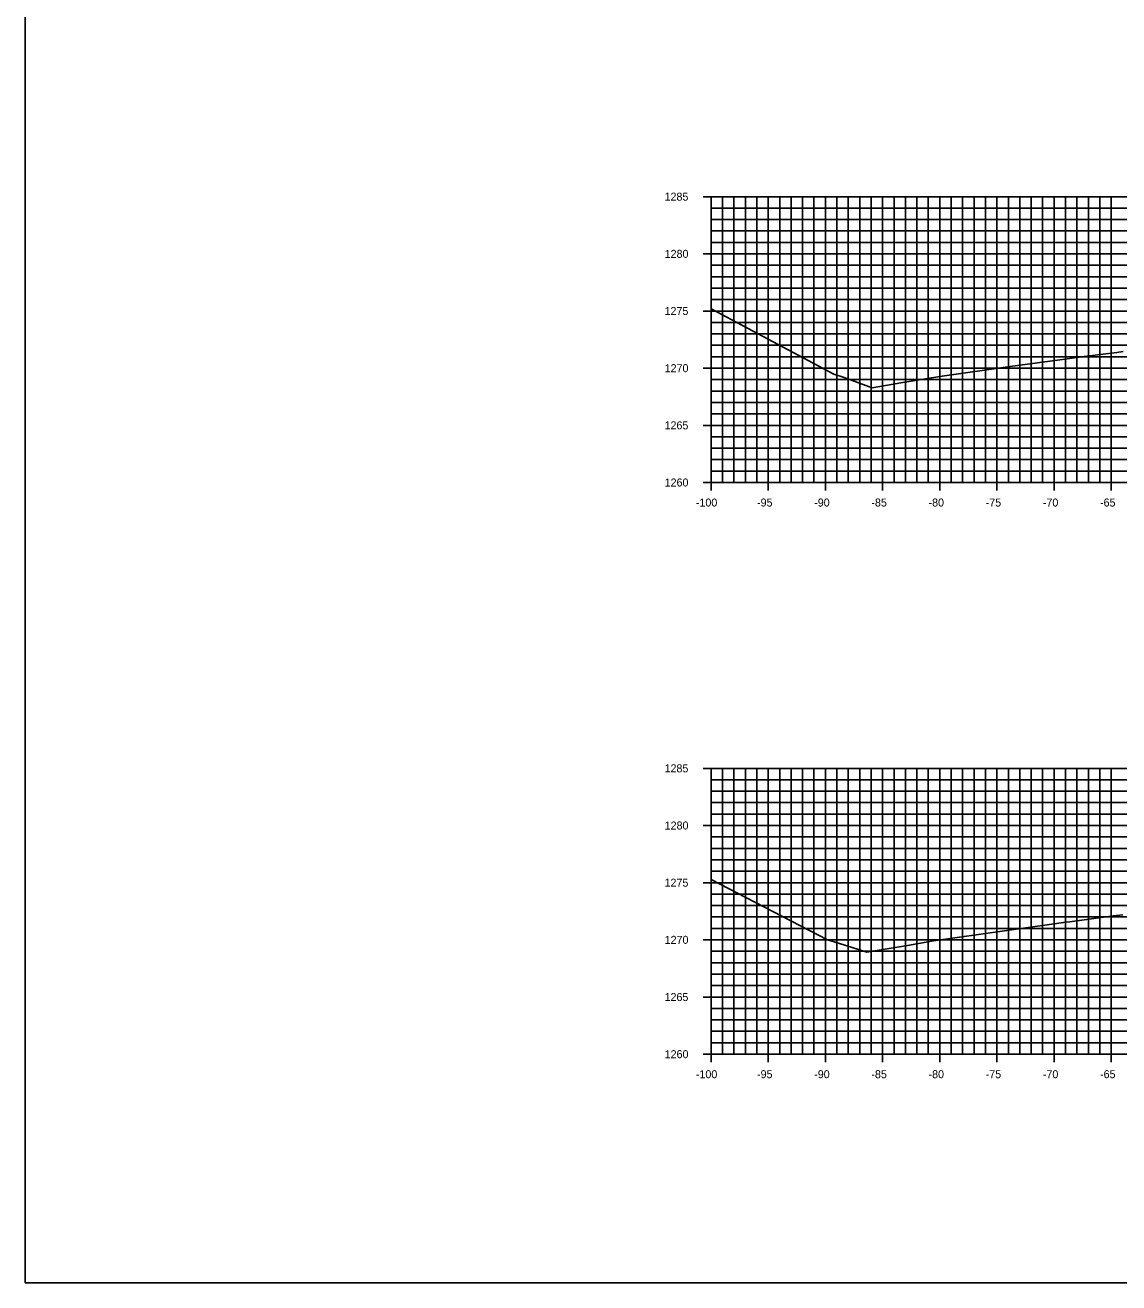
# Model space of a CAD drawing. Extents: x 674939 to 678919, y 750652 to 765176.
# Drawn here: x 678578.5 to 678674.2, y 756672.6 to 756782.6 of the extents above; entities that cross this region are included whole.
import ezdxf

# ---------------------------------------------------------------- set-up
doc = ezdxf.new("R2010")
doc.units = 0
for name, color, linetype in [('R_Axis', 7, 'Continuous'), ('R_Axis Annot', 7, 'Continuous'), ('R_Exist Surface', 7, 'Continuous'), ('R_Grid', 7, 'Continuous'), ('R_No Plot', 7, 'Continuous')]:
    doc.layers.add(name, color=color, linetype=linetype)

msp = doc.modelspace()

# ---------------------------------------------------------------- linework, layer by layer
at = {"layer": 'R_Axis'}
for p, q in [((678637.83, 756767.55), (678639.23, 756767.55)), ((678638.53, 756742.55), (678638.53, 756767.55)), ((678638.53, 756766.55), (678638.88, 756766.55)), ((678638.53, 756765.55), (678638.88, 756765.55)), ((678638.53, 756764.55), (678638.88, 756764.55)), ((678638.53, 756763.55), (678638.88, 756763.55)), ((678637.83, 756762.55), (678639.23, 756762.55)), ((678638.53, 756761.55), (678638.88, 756761.55)), ((678638.53, 756760.55), (678638.88, 756760.55)), ((678638.53, 756759.55), (678638.88, 756759.55)), ((678638.53, 756758.55), (678638.88, 756758.55)), ((678637.83, 756757.55), (678639.23, 756757.55)), ((678638.53, 756756.55), (678638.88, 756756.55)), ((678638.53, 756755.55), (678638.88, 756755.55)), ((678638.53, 756754.55), (678638.88, 756754.55)), ((678638.53, 756753.55), (678638.88, 756753.55)), ((678637.83, 756752.55), (678639.23, 756752.55)), ((678638.53, 756751.55), (678638.88, 756751.55)), ((678638.53, 756750.55), (678638.88, 756750.55)), ((678638.53, 756749.55), (678638.88, 756749.55)), ((678638.53, 756748.55), (678638.88, 756748.55)), ((678637.83, 756747.55), (678639.23, 756747.55)), ((678638.53, 756746.55), (678638.88, 756746.55)), ((678638.53, 756745.55), (678638.88, 756745.55)), ((678638.53, 756744.55), (678638.88, 756744.55)), ((678638.53, 756743.55), (678638.88, 756743.55)), ((678638.53, 756741.85), (678638.53, 756743.25)), ((678643.53, 756741.85), (678643.53, 756743.25)), ((678648.53, 756741.85), (678648.53, 756743.25)), ((678653.53, 756741.85), (678653.53, 756743.25)), ((678658.53, 756741.85), (678658.53, 756743.25)), ((678663.53, 756741.85), (678663.53, 756743.25)), ((678668.53, 756741.85), (678668.53, 756743.25)), ((678673.53, 756741.85), (678673.53, 756743.25)), ((678637.83, 756742.55), (678639.23, 756742.55)), ((678638.53, 756742.55), (678838.53, 756742.55)), ((678637.83, 756717.55), (678639.23, 756717.55)), ((678638.53, 756692.55), (678638.53, 756717.55)), ((678638.53, 756716.55), (678638.88, 756716.55)), ((678638.53, 756715.55), (678638.88, 756715.55)), ((678638.53, 756714.55), (678638.88, 756714.55)), ((678638.53, 756713.55), (678638.88, 756713.55)), ((678637.83, 756712.55), (678639.23, 756712.55)), ((678638.53, 756711.55), (678638.88, 756711.55)), ((678638.53, 756710.55), (678638.88, 756710.55)), ((678638.53, 756709.55), (678638.88, 756709.55)), ((678638.53, 756708.55), (678638.88, 756708.55)), ((678637.83, 756707.55), (678639.23, 756707.55)), ((678638.53, 756706.55), (678638.88, 756706.55)), ((678638.53, 756705.55), (678638.88, 756705.55)), ((678638.53, 756704.55), (678638.88, 756704.55)), ((678638.53, 756703.55), (678638.88, 756703.55)), ((678637.83, 756702.55), (678639.23, 756702.55)), ((678638.53, 756701.55), (678638.88, 756701.55)), ((678638.53, 756700.55), (678638.88, 756700.55)), ((678638.53, 756699.55), (678638.88, 756699.55)), ((678638.53, 756698.55), (678638.88, 756698.55)), ((678637.83, 756697.55), (678639.23, 756697.55)), ((678638.53, 756696.55), (678638.88, 756696.55)), ((678638.53, 756695.55), (678638.88, 756695.55)), ((678638.53, 756694.55), (678638.88, 756694.55)), ((678638.53, 756693.55), (678638.88, 756693.55)), ((678637.83, 756692.55), (678639.23, 756692.55)), ((678638.53, 756691.85), (678638.53, 756693.25)), ((678638.53, 756692.55), (678838.53, 756692.55)), ((678643.53, 756691.85), (678643.53, 756693.25)), ((678648.53, 756691.85), (678648.53, 756693.25)), ((678653.53, 756691.85), (678653.53, 756693.25)), ((678658.53, 756691.85), (678658.53, 756693.25)), ((678663.53, 756691.85), (678663.53, 756693.25)), ((678668.53, 756691.85), (678668.53, 756693.25)), ((678673.53, 756691.85), (678673.53, 756693.25))]:
    msp.add_line(p, q, dxfattribs=at)
at = {"layer": 'R_Exist Surface'}
for points in [[(678638.53, 756757.73), (678641.72, 756756.04), (678649.26, 756752.04), (678650.17, 756751.74), (678652.61, 756750.82), (678655.13, 756751.26), (678658.54, 756751.82), (678664.68, 756752.69), (678669.48, 756753.33), (678671.17, 756753.56), (678674.02, 756753.93), (678674.57, 756754.01)], [(678638.53, 756707.83), (678641.56, 756706.26), (678648.72, 756702.56), (678649.68, 756702.25), (678652.14, 756701.46), (678655.72, 756702.06), (678657.98, 756702.45), (678668.32, 756703.91), (678669.56, 756704.09), (678669.92, 756704.14), (678673.69, 756704.65), (678673.72, 756704.65), (678674.53, 756704.75)]]:
    msp.add_lwpolyline(points, dxfattribs=at)
at = {"layer": 'R_Grid'}
for p, q in [((678638.53, 756767.55), (678838.53, 756767.55)), ((678638.53, 756742.55), (678638.53, 756767.55)), ((678639.53, 756742.55), (678639.53, 756767.55)), ((678640.53, 756742.55), (678640.53, 756767.55)), ((678641.53, 756742.55), (678641.53, 756767.55)), ((678642.53, 756742.55), (678642.53, 756767.55)), ((678643.53, 756742.55), (678643.53, 756767.55)), ((678644.53, 756742.55), (678644.53, 756767.55)), ((678645.53, 756742.55), (678645.53, 756767.55)), ((678646.53, 756742.55), (678646.53, 756767.55)), ((678647.53, 756742.55), (678647.53, 756767.55)), ((678648.53, 756742.55), (678648.53, 756767.55)), ((678649.53, 756742.55), (678649.53, 756767.55)), ((678650.53, 756742.55), (678650.53, 756767.55)), ((678651.53, 756742.55), (678651.53, 756767.55)), ((678652.53, 756742.55), (678652.53, 756767.55)), ((678653.53, 756742.55), (678653.53, 756767.55)), ((678654.53, 756742.55), (678654.53, 756767.55)), ((678655.53, 756742.55), (678655.53, 756767.55)), ((678656.53, 756742.55), (678656.53, 756767.55)), ((678657.53, 756742.55), (678657.53, 756767.55)), ((678658.53, 756742.55), (678658.53, 756767.55)), ((678659.53, 756742.55), (678659.53, 756767.55)), ((678660.53, 756742.55), (678660.53, 756767.55)), ((678661.53, 756742.55), (678661.53, 756767.55)), ((678662.53, 756742.55), (678662.53, 756767.55)), ((678663.53, 756742.55), (678663.53, 756767.55)), ((678664.53, 756742.55), (678664.53, 756767.55)), ((678665.53, 756742.55), (678665.53, 756767.55)), ((678666.53, 756742.55), (678666.53, 756767.55)), ((678667.53, 756742.55), (678667.53, 756767.55)), ((678668.53, 756742.55), (678668.53, 756767.55)), ((678669.53, 756742.55), (678669.53, 756767.55)), ((678670.53, 756742.55), (678670.53, 756767.55)), ((678671.53, 756742.55), (678671.53, 756767.55)), ((678672.53, 756742.55), (678672.53, 756767.55)), ((678673.53, 756742.55), (678673.53, 756767.55)), ((678638.53, 756766.55), (678838.53, 756766.55)), ((678638.53, 756765.55), (678838.53, 756765.55)), ((678638.53, 756764.55), (678838.53, 756764.55)), ((678638.53, 756763.55), (678838.53, 756763.55)), ((678638.53, 756762.55), (678838.53, 756762.55)), ((678638.53, 756761.55), (678838.53, 756761.55)), ((678638.53, 756760.55), (678838.53, 756760.55)), ((678638.53, 756759.55), (678838.53, 756759.55)), ((678638.53, 756758.55), (678838.53, 756758.55)), ((678638.53, 756757.55), (678838.53, 756757.55)), ((678638.53, 756756.55), (678838.53, 756756.55)), ((678638.53, 756755.55), (678838.53, 756755.55)), ((678638.53, 756754.55), (678838.53, 756754.55)), ((678638.53, 756753.55), (678838.53, 756753.55)), ((678638.53, 756752.55), (678838.53, 756752.55)), ((678638.53, 756751.55), (678838.53, 756751.55)), ((678638.53, 756750.55), (678838.53, 756750.55)), ((678638.53, 756749.55), (678838.53, 756749.55)), ((678638.53, 756748.55), (678838.53, 756748.55)), ((678638.53, 756747.55), (678838.53, 756747.55)), ((678638.53, 756746.55), (678838.53, 756746.55)), ((678638.53, 756745.55), (678838.53, 756745.55)), ((678638.53, 756744.55), (678838.53, 756744.55)), ((678638.53, 756743.55), (678838.53, 756743.55)), ((678638.53, 756742.55), (678838.53, 756742.55)), ((678638.53, 756717.55), (678838.53, 756717.55)), ((678638.53, 756692.55), (678638.53, 756717.55)), ((678639.53, 756692.55), (678639.53, 756717.55)), ((678640.53, 756692.55), (678640.53, 756717.55)), ((678641.53, 756692.55), (678641.53, 756717.55)), ((678642.53, 756692.55), (678642.53, 756717.55)), ((678643.53, 756692.55), (678643.53, 756717.55)), ((678644.53, 756692.55), (678644.53, 756717.55)), ((678645.53, 756692.55), (678645.53, 756717.55)), ((678646.53, 756692.55), (678646.53, 756717.55)), ((678647.53, 756692.55), (678647.53, 756717.55)), ((678648.53, 756692.55), (678648.53, 756717.55)), ((678649.53, 756692.55), (678649.53, 756717.55)), ((678650.53, 756692.55), (678650.53, 756717.55)), ((678651.53, 756692.55), (678651.53, 756717.55)), ((678652.53, 756692.55), (678652.53, 756717.55)), ((678653.53, 756692.55), (678653.53, 756717.55)), ((678654.53, 756692.55), (678654.53, 756717.55)), ((678655.53, 756692.55), (678655.53, 756717.55)), ((678656.53, 756692.55), (678656.53, 756717.55)), ((678657.53, 756692.55), (678657.53, 756717.55)), ((678658.53, 756692.55), (678658.53, 756717.55)), ((678659.53, 756692.55), (678659.53, 756717.55)), ((678660.53, 756692.55), (678660.53, 756717.55)), ((678661.53, 756692.55), (678661.53, 756717.55)), ((678662.53, 756692.55), (678662.53, 756717.55)), ((678663.53, 756692.55), (678663.53, 756717.55)), ((678664.53, 756692.55), (678664.53, 756717.55)), ((678665.53, 756692.55), (678665.53, 756717.55)), ((678666.53, 756692.55), (678666.53, 756717.55)), ((678667.53, 756692.55), (678667.53, 756717.55)), ((678668.53, 756692.55), (678668.53, 756717.55)), ((678669.53, 756692.55), (678669.53, 756717.55)), ((678670.53, 756692.55), (678670.53, 756717.55)), ((678671.53, 756692.55), (678671.53, 756717.55)), ((678672.53, 756692.55), (678672.53, 756717.55)), ((678673.53, 756692.55), (678673.53, 756717.55)), ((678638.53, 756716.55), (678838.53, 756716.55)), ((678638.53, 756715.55), (678838.53, 756715.55)), ((678638.53, 756714.55), (678838.53, 756714.55)), ((678638.53, 756713.55), (678838.53, 756713.55)), ((678638.53, 756712.55), (678838.53, 756712.55)), ((678638.53, 756711.55), (678838.53, 756711.55)), ((678638.53, 756710.55), (678838.53, 756710.55)), ((678638.53, 756709.55), (678838.53, 756709.55)), ((678638.53, 756708.55), (678838.53, 756708.55)), ((678638.53, 756707.55), (678838.53, 756707.55)), ((678638.53, 756706.55), (678838.53, 756706.55)), ((678638.53, 756705.55), (678838.53, 756705.55)), ((678638.53, 756704.55), (678838.53, 756704.55)), ((678638.53, 756703.55), (678838.53, 756703.55)), ((678638.53, 756702.55), (678838.53, 756702.55)), ((678638.53, 756701.55), (678838.53, 756701.55)), ((678638.53, 756700.55), (678838.53, 756700.55)), ((678638.53, 756699.55), (678838.53, 756699.55)), ((678638.53, 756698.55), (678838.53, 756698.55)), ((678638.53, 756697.55), (678838.53, 756697.55)), ((678638.53, 756696.55), (678838.53, 756696.55)), ((678638.53, 756695.55), (678838.53, 756695.55)), ((678638.53, 756694.55), (678838.53, 756694.55)), ((678638.53, 756693.55), (678838.53, 756693.55)), ((678638.53, 756692.55), (678838.53, 756692.55))]:
    msp.add_line(p, q, dxfattribs=at)
at = {"layer": 'R_No Plot'}
msp.add_lwpolyline([(678578.53, 756672.55), (678918.53, 756672.55), (678918.53, 756892.55), (678578.53, 756892.55)], close=True, dxfattribs=at)

# ---------------------------------------------------------------- texts
at = {"layer": 'R_Axis Annot'}
for s, p in [('1285', (678634.46, 756767.2)), ('1280', (678634.47, 756762.2)), ('1275', (678634.46, 756757.2)), ('1270', (678634.47, 756752.2)), ('1265', (678634.46, 756747.2)), ('1260', (678634.47, 756742.2)), ('-100', (678637.2, 756740.45)), ('-95', (678642.55, 756740.45)), ('-90', (678647.55, 756740.45)), ('-85', (678652.55, 756740.45)), ('-80', (678657.55, 756740.45)), ('-75', (678662.55, 756740.45)), ('-70', (678667.55, 756740.45)), ('-65', (678672.55, 756740.45)), ('1285', (678634.46, 756717.2)), ('1280', (678634.47, 756712.2)), ('1275', (678634.46, 756707.2)), ('1270', (678634.47, 756702.2)), ('1265', (678634.46, 756697.2)), ('1260', (678634.47, 756692.2)), ('-100', (678637.2, 756690.45)), ('-95', (678642.55, 756690.45)), ('-90', (678647.55, 756690.45)), ('-85', (678652.55, 756690.45)), ('-80', (678657.55, 756690.45)), ('-75', (678662.55, 756690.45)), ('-70', (678667.55, 756690.45)), ('-65', (678672.55, 756690.45))]:
    msp.add_text(s, height=0.7, dxfattribs=at).set_placement(p)

doc.saveas('drawing.dxf')
